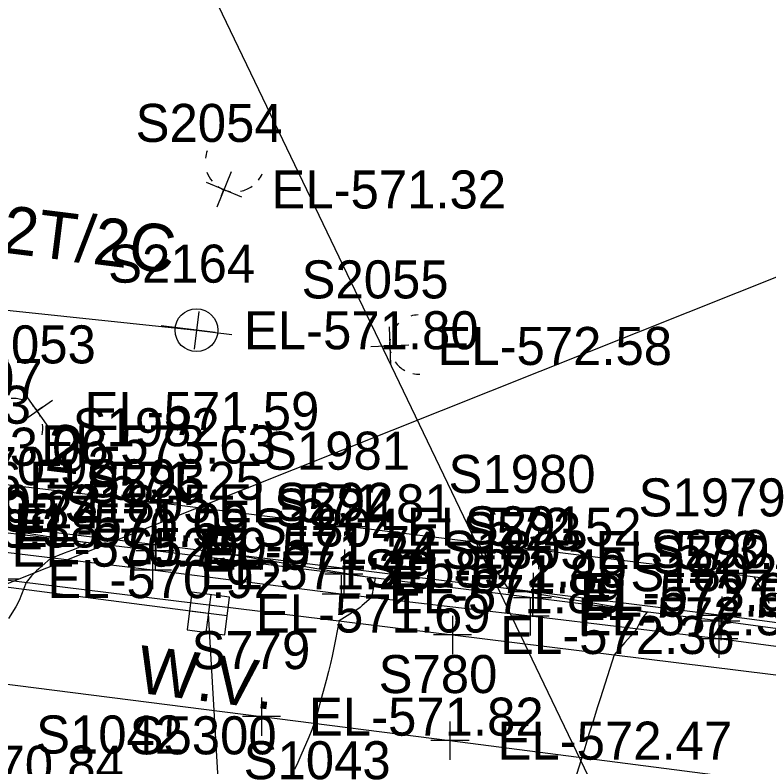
# Model space of a CAD drawing. Extents: x 1724534 to 1727318, y 657156 to 660047.
# Drawn here: x 1725826.2 to 1725905.5, y 658583.4 to 658662.4 of the extents above; entities that cross this region are included whole.
import ezdxf

# ---------------------------------------------------------------- set-up
doc = ezdxf.new("R2010")
doc.units = 0
for name, color, linetype in [('SURVEY - CENTERLINE - Preliminary Text', 7, 'Continuous'), ('SURVEY - CONTOURS - Intermediate with optional Text', 7, 'Continuous'), ('SURVEY - DRAINAGE - Storm Sewer', 7, 'Continuous'), ('SURVEY - DTM - Breaklines', 7, 'Continuous'), ('SURVEY - DTM - Breaklines - Points - Elevations', 7, 'Continuous'), ('SURVEY - DTM - Breaklines - Points - Locators', 7, 'Continuous'), ('SURVEY - DTM - Breaklines - Points - Numbers', 7, 'Continuous'), ('SURVEY - ROADSIDE BARRIERS - Points - Elevations', 7, 'Continuous'), ('SURVEY - ROADSIDE BARRIERS - Points - Numbers', 7, 'Continuous'), ('SURVEY - TRAFFIC CONTROL - Pavement Marking - Points - Elevations', 7, 'Continuous'), ('SURVEY - TRAFFIC CONTROL - Pavement Marking - Points - Locators', 7, 'Continuous'), ('SURVEY - TRAFFIC CONTROL - Pavement Marking - Points - Numbers', 7, 'Continuous'), ('SURVEY - TRAFFIC CONTROL - Pavement Marking with Text', 7, 'Continuous'), ('SURVEY - TRANSPORTATION - Features', 7, 'Continuous'), ('SURVEY - TRANSPORTATION - Features - Points - Elevations', 7, 'Continuous'), ('SURVEY - TRANSPORTATION - Features - Points - Locators', 7, 'Continuous'), ('SURVEY - TRANSPORTATION - Features - Points - Numbers', 7, 'Continuous'), ('SURVEY - TRANSPORTATION - Roads', 7, 'Continuous'), ('SURVEY - TRANSPORTATION - Roads - Points - Elevations', 7, 'Continuous'), ('SURVEY - TRANSPORTATION - Roads - Points - Locators', 7, 'Continuous'), ('SURVEY - TRANSPORTATION - Roads - Points - Numbers', 7, 'Continuous'), ('SURVEY - UTILITIES - Overhead Wire Crossings', 7, 'Continuous'), ('SURVEY - UTILITIES - Poles and Miscellaneous - Points - Elevations', 7, 'Continuous'), ('SURVEY - UTILITIES - Poles and Miscellaneous - Points - Locators', 7, 'Continuous'), ('SURVEY - UTILITIES - Poles and Miscellaneous - Points - Numbers', 7, 'Continuous'), ('SURVEY - UTILITIES - Poles and Miscellaneous with Text', 7, 'Continuous'), ('SURVEY - UTILITIES - Water - Points - Elevations', 7, 'Continuous'), ('SURVEY - UTILITIES - Water - Points - Locators', 7, 'Continuous'), ('SURVEY - UTILITIES - Water - Points - Numbers', 7, 'Continuous'), ('SURVEY - UTILITIES - Water with Text', 7, 'Continuous')]:
    doc.layers.add(name, color=color, linetype=linetype)

msp = doc.modelspace()

# ---------------------------------------------------------------- linework, layer by layer
at = {"layer": 'SURVEY - CENTERLINE - Preliminary Text'}
msp.add_line((1725772.853, 658581.708), (1725925.415, 658642.543), dxfattribs=at)
at = {"layer": 'SURVEY - CONTOURS - Intermediate with optional Text'}
for points in [[(1725846.883, 658610.445), (1725847.229, 658609.737), (1725847.817, 658608.493), (1725849.121, 658605.72), (1725851.058, 658605.397), (1725851.572, 658605.312), (1725852.077, 658605.228), (1725856.35, 658604.519), (1725858.166, 658604.22), (1725859.028, 658604.079), (1725859.647, 658603.976), (1725860.528, 658603.83), (1725860.808, 658603.784), (1725860.87, 658603.774), (1725861.796, 658603.619), (1725864.101, 658603.234), (1725863.926, 658602.302), (1725863.891, 658602.114), (1725863.857, 658601.949), (1725863.827, 658601.807), (1725863.8, 658601.687), (1725863.678, 658601.184), (1725862.72, 658600.344), (1725862.503, 658600.163), (1725862.262, 658599.98), (1725861.998, 658599.795), (1725861.709, 658599.609), (1725860.307, 658598.732), (1725859.707, 658595.722), (1725859.562, 658595.036), (1725859.385, 658594.269), (1725859.175, 658593.421), (1725858.933, 658592.491), (1725858.245, 658589.903), (1725857.98, 658588.963), (1725857.702, 658588.086), (1725857.412, 658587.272), (1725857.108, 658586.519), (1725856.281, 658584.597), (1725855.954, 658583.868), (1725855.595, 658583.124)], [(1725826.087, 658608.215), (1725826.634, 658608.127), (1725827.177, 658608.039), (1725828.622, 658607.807), (1725829.121, 658607.726), (1725829.534, 658607.66), (1725829.861, 658607.607), (1725830.103, 658607.568), (1725830.858, 658607.447), (1725831.134, 658607.403), (1725831.462, 658607.35), (1725831.841, 658607.289), (1725833.73, 658606.984), (1725833.032, 658606.535), (1725832.865, 658606.438), (1725832.663, 658606.339), (1725832.427, 658606.238), (1725832.156, 658606.135), (1725831.387, 658605.859), (1725831.127, 658605.764), (1725830.923, 658605.689), (1725830.776, 658605.632), (1725830.685, 658605.594), (1725830.518, 658605.518), (1725830.456, 658605.491), (1725830.393, 658605.466), (1725830.33, 658605.445), (1725830.267, 658605.427), (1725829.971, 658605.349), (1725828.715, 658604.232), (1725828.465, 658604.005), (1725828.252, 658603.801), (1725828.076, 658603.622), (1725827.938, 658603.466), (1725827.378, 658602.797), (1725826.642, 658600.898), (1725826.282, 658600.218), (1725825.518, 658598.99)], [(1725874.865, 658606.982), (1725875.917, 658605.357), (1725876.397, 658604.627), (1725878.066, 658602.116), (1725880.271, 658601.747), (1725880.867, 658601.648), (1725881.631, 658601.52), (1725886.772, 658600.663), (1725888.832, 658600.319), (1725892.705, 658599.672), (1725892.341, 658599.253), (1725892.261, 658599.152), (1725892.178, 658599.029), (1725892.091, 658598.884), (1725892.001, 658598.717), (1725891.571, 658597.887), (1725890.939, 658597.147), (1725890.358, 658596.477), (1725889.218, 658595.164), (1725887.782, 658590.658), (1725887.444, 658589.589), (1725887.043, 658588.312), (1725886.58, 658586.829), (1725886.056, 658585.138), (1725884.574, 658580.353)], [(1725903.921, 658603.36), (1725904.459, 658602.513), (1725904.579, 658602.319), (1725904.708, 658602.102), (1725904.846, 658601.861), (1725904.993, 658601.596), (1725905.542, 658600.595)]]:
    msp.add_lwpolyline(points, dxfattribs=at)
at = {"layer": 'SURVEY - DRAINAGE - Storm Sewer'}
msp.add_line((1725899.095, 658556.269), (1725845.926, 658666.932), dxfattribs=at)
at = {"layer": 'SURVEY - DTM - Breaklines'}
msp.add_lwpolyline([(1725923.442, 658596.261), (1725920.349, 658596.664), (1725900.537, 658599.315), (1725880.703, 658601.788), (1725860.867, 658604.256), (1725841.017, 658606.73), (1725821.164, 658609.108), (1725805.637, 658611.084), (1725785.8, 658613.524), (1725762.697, 658616.458), (1725748.853, 658618.143), (1725745.613, 658618.535), (1725725.762, 658620.955), (1725705.909, 658623.419), (1725686.061, 658625.875)], dxfattribs=at)
at = {"layer": 'SURVEY - DTM - Breaklines - Points - Locators'}
for p, q in [((1725841.017, 658608.73), (1725841.017, 658604.73)), ((1725843.017, 658606.73), (1725839.017, 658606.73)), ((1725860.867, 658606.256), (1725860.867, 658602.256)), ((1725862.867, 658604.256), (1725858.867, 658604.256)), ((1725880.703, 658603.788), (1725880.703, 658599.788)), ((1725882.703, 658601.788), (1725878.703, 658601.788)), ((1725900.537, 658601.315), (1725900.537, 658597.315)), ((1725902.537, 658599.315), (1725898.537, 658599.315))]:
    msp.add_line(p, q, dxfattribs=at)
at = {"layer": 'SURVEY - TRAFFIC CONTROL - Pavement Marking - Points - Locators'}
for p, q in [((1725852.127, 658590.674), (1725852.127, 658586.674)), ((1725854.127, 658588.674), (1725850.127, 658588.674)), ((1725871.961, 658588.151), (1725871.961, 658584.151)), ((1725873.961, 658586.151), (1725869.961, 658586.151))]:
    msp.add_line(p, q, dxfattribs=at)
at = {"layer": 'SURVEY - TRAFFIC CONTROL - Pavement Marking with Text'}
msp.add_lwpolyline([(1725469.93, 658636.195), (1725476.311, 658635.371), (1725478.295, 658635.122), (1725516.011, 658630.481), (1725599.369, 658620.164), (1725678.757, 658610.338), (1725738.298, 658602.97), (1725780.716, 658597.719), (1725790.639, 658596.491), (1725852.127, 658588.674), (1725871.961, 658586.151), (1725916.153, 658580.463)], dxfattribs=at)
at = {"layer": 'SURVEY - TRANSPORTATION - Features'}
for points in [[(1725923.364, 658595.652), (1725920.271, 658596.054), (1725900.459, 658598.705), (1725880.625, 658601.178), (1725860.79, 658603.646), (1725840.941, 658606.12), (1725821.088, 658608.498), (1725805.562, 658610.474), (1725785.723, 658612.914), (1725762.62, 658615.849), (1725748.776, 658617.533), (1725745.535, 658617.925), (1725725.684, 658620.345), (1725705.833, 658622.809), (1725685.985, 658625.265)], [(1725924.124, 658601.632), (1725920.917, 658601.133), (1725901.098, 658603.73), (1725881.263, 658606.193), (1725861.425, 658608.639), (1725841.56, 658611.106), (1725821.706, 658613.473), (1725806.126, 658615.02), (1725786.298, 658617.46), (1725763.169, 658620.191), (1725751.211, 658621.652), (1725751.19, 658622.534), (1725749.441, 658623.208)], [(1725923.129, 658593.802), (1725920.036, 658594.204), (1725900.224, 658596.854), (1725880.377, 658599.224), (1725860.524, 658601.554), (1725840.686, 658604.065), (1725820.833, 658606.443), (1725805.311, 658608.457), (1725785.478, 658610.975), (1725762.374, 658613.908), (1725762.62, 658615.849)]]:
    msp.add_lwpolyline(points, dxfattribs=at)
at = {"layer": 'SURVEY - TRANSPORTATION - Features - Points - Locators'}
for p, q in [((1725841.56, 658613.106), (1725841.56, 658609.106)), ((1725843.56, 658611.106), (1725839.56, 658611.106)), ((1725861.425, 658610.639), (1725861.425, 658606.639)), ((1725840.941, 658608.12), (1725840.941, 658604.12)), ((1725863.425, 658608.639), (1725859.425, 658608.639)), ((1725881.263, 658608.193), (1725881.263, 658604.193)), ((1725842.941, 658606.12), (1725838.941, 658606.12)), ((1725840.686, 658606.065), (1725840.686, 658602.065)), ((1725883.263, 658606.193), (1725879.263, 658606.193)), ((1725901.098, 658605.73), (1725901.098, 658601.73)), ((1725860.79, 658605.646), (1725860.79, 658601.646)), ((1725842.686, 658604.065), (1725838.686, 658604.065)), ((1725862.79, 658603.646), (1725858.79, 658603.646)), ((1725860.524, 658603.554), (1725860.524, 658599.554)), ((1725903.098, 658603.73), (1725899.098, 658603.73)), ((1725880.625, 658603.178), (1725880.625, 658599.178)), ((1725862.524, 658601.554), (1725858.524, 658601.554)), ((1725882.625, 658601.178), (1725878.625, 658601.178)), ((1725880.377, 658601.224), (1725880.377, 658597.224)), ((1725900.459, 658600.705), (1725900.459, 658596.705)), ((1725882.377, 658599.224), (1725878.377, 658599.224)), ((1725902.459, 658598.705), (1725898.459, 658598.705)), ((1725900.224, 658598.854), (1725900.224, 658594.854)), ((1725902.224, 658596.854), (1725898.224, 658596.854))]:
    msp.add_line(p, q, dxfattribs=at)
at = {"layer": 'SURVEY - TRANSPORTATION - Roads'}
msp.add_lwpolyline([(1725603.861, 658630.44), (1725726.921, 658615.268), (1725763.101, 658610.806), (1725790.88, 658607.344), (1725824.612, 658603.138), (1725872.227, 658597.261), (1725926.076, 658590.615)], dxfattribs=at)
at = {"layer": 'SURVEY - TRANSPORTATION - Roads - Points - Locators'}
for p, q in [((1725826.612, 658603.138), (1725822.612, 658603.138)), ((1725872.227, 658599.261), (1725872.227, 658595.261)), ((1725874.227, 658597.261), (1725870.227, 658597.261))]:
    msp.add_line(p, q, dxfattribs=at)
at = {"layer": 'SURVEY - UTILITIES - Overhead Wire Crossings'}
msp.add_line((1725320.87, 658684.66), (1725845.289, 658629.305), dxfattribs=at)
at = {"layer": 'SURVEY - UTILITIES - Poles and Miscellaneous - Points - Locators'}
for p, q in [((1725848.936, 658645.956), (1725847.422, 658642.254)), ((1725846.328, 658644.862), (1725850.03, 658643.348)), ((1725845.532, 658631.29), (1725845.046, 658627.32)), ((1725847.274, 658629.062), (1725843.304, 658629.548)), ((1725865.557, 658629.649), (1725865.711, 658625.651)), ((1725867.633, 658627.727), (1725863.635, 658627.573)), ((1725829.685, 658619.181), (1725827.381, 658622.451)), ((1725826.898, 658619.664), (1725830.168, 658621.968))]:
    msp.add_line(p, q, dxfattribs=at)
at = {"layer": 'SURVEY - UTILITIES - Poles and Miscellaneous with Text'}
for p, q in [((1725847.914, 658643.457), (1725848.179, 658644.105)), ((1725845.289, 658629.305), (1725841.567, 658629.76)), ((1725845.289, 658629.305), (1725849.011, 658628.85)), ((1725864.935, 658627.623), (1725865.634, 658627.65)), ((1725829.105, 658621.219), (1725828.533, 658620.816))]:
    msp.add_line(p, q, dxfattribs=at)
msp.add_circle((1725845.289, 658629.305), 2.25, dxfattribs=at)
for centre, start, end in [((1725849.329, 658646.984), 157.76371, 172.38458), ((1725849.329, 658646.984), 199.64158, 219.98409), ((1725849.329, 658646.984), 322.95024, 336.83966), ((1725849.329, 658646.984), 235.28464, 261.79995), ((1725849.329, 658646.984), 281.32645, 306.09649), ((1725868.731, 658627.794), 92.2058, 106.82667), ((1725868.731, 658627.794), 134.08367, 154.42618), ((1725868.731, 658627.794), 169.72673, 196.24204), ((1725868.731, 658627.794), 215.76854, 240.53858), ((1725868.731, 658627.794), 257.39233, 271.28175), ((1725826.014, 658619.01), 68.73872, 93.50876), ((1725826.014, 658619.01), 22.6969, 49.21222), ((1725826.014, 658619.01), 347.05385, 7.39636), ((1725826.014, 658619.01), 305.17598, 319.79685)]:
    msp.add_arc(centre, 3.125, start, end, dxfattribs=at)
at = {"layer": 'SURVEY - UTILITIES - Water - Points - Locators'}
for p, q in [((1725846.804, 658601.504), (1725846.292, 658597.536)), ((1725848.532, 658599.264), (1725844.564, 658599.776))]:
    msp.add_line(p, q, dxfattribs=at)
at = {"layer": 'SURVEY - UTILITIES - Water with Text'}
msp.add_line((1725846.548, 658599.52), (1725846.548, 658599.52), dxfattribs=at)
for points in [[(1725847.724, 658579.712), (1725846.548, 658599.52), (1725380.522, 658660.104)], [(1725844.82, 658601.759), (1725844.309, 658597.792), (1725848.276, 658597.281), (1725848.787, 658601.248), (1725844.82, 658601.759)]]:
    msp.add_lwpolyline(points, dxfattribs=at)

# ---------------------------------------------------------------- texts
at = {"layer": 'SURVEY - DTM - Breaklines - Points - Elevations'}
for s, p in [('EL-570.72', (1725810.637, 658609.084)), ('EL-571.09', (1725826.164, 658607.108)), ('EL-571.72', (1725846.017, 658604.73)), ('EL-572.40', (1725865.867, 658602.256)), ('EL-573.09', (1725885.703, 658599.788))]:
    msp.add_text(s, height=4, dxfattribs=at).set_placement(p)
at = {"layer": 'SURVEY - DTM - Breaklines - Points - Numbers'}
for s, p in [('S293', (1725833.681, 658611.73)), ('S292', (1725853.531, 658609.256)), ('S291', (1725873.525, 658606.788)), ('S290', (1725893.028, 658604.315))]:
    msp.add_text(s, height=4, dxfattribs=at).set_placement(p)
at = {"layer": 'SURVEY - ROADSIDE BARRIERS - Points - Elevations'}
for s, p in [('EL-573.63', (1725828.955, 658615.289)), ('EL-573.06', (1725811.38, 658615.061))]:
    msp.add_text(s, height=4, dxfattribs=at).set_placement(p)
at = {"layer": 'SURVEY - ROADSIDE BARRIERS - Points - Numbers'}
msp.add_text('S707', height=4, dxfattribs=at).set_placement((1725816.619, 658622.289))
at = {"layer": 'SURVEY - TRAFFIC CONTROL - Pavement Marking - Points - Elevations'}
for s, p in [('EL-571.82', (1725857.127, 658586.674)), ('EL-572.47', (1725876.961, 658584.151)), ('EL-570.84', (1725812.969, 658581.629))]:
    msp.add_text(s, height=4, dxfattribs=at).set_placement(p)
at = {"layer": 'SURVEY - TRAFFIC CONTROL - Pavement Marking - Points - Numbers'}
for s, p in [('S779', (1725844.775, 658593.674)), ('S780', (1725864.452, 658591.151)), ('S1042', (1725828.428, 658584.798)), ('S1043', (1725850.253, 658582.092))]:
    msp.add_text(s, height=4, dxfattribs=at).set_placement(p)
at = {"layer": 'SURVEY - TRANSPORTATION - Features - Points - Elevations'}
for s, p in [('EL-570.92', (1725812.126, 658613.02)), ('EL-571.25', (1725827.706, 658611.473)), ('EL-571.81', (1725847.56, 658609.106)), ('EL-570.24', (1725810.562, 658608.474)), ('EL-570.38', (1725810.311, 658606.457)), ('EL-570.58', (1725826.088, 658606.498)), ('EL-572.52', (1725867.425, 658606.639)), ('EL-570.75', (1725825.833, 658604.443)), ('EL-571.24', (1725845.941, 658604.12)), ('EL-573.23', (1725887.263, 658604.193)), ('EL-571.29', (1725845.686, 658602.065)), ('EL-571.88', (1725865.79, 658601.646)), ('EL-571.89', (1725865.524, 658599.554)), ('EL-572.58', (1725885.625, 658599.178)), ('EL-572.58', (1725885.377, 658597.224))]:
    msp.add_text(s, height=4, dxfattribs=at).set_placement(p)
at = {"layer": 'SURVEY - TRANSPORTATION - Features - Points - Numbers'}
for s, p in [('S1983', (1725812.418, 658619.473)), ('S1982', (1725832.272, 658617.106)), ('S1981', (1725852.295, 658614.639)), ('S1980', (1725871.802, 658612.193)), ('S1806', (1725811.435, 658611.443)), ('S525', (1725833.605, 658611.12)), ('S1979', (1725891.795, 658609.73)), ('S1805', (1725831.398, 658609.065)), ('S524', (1725853.454, 658608.646)), ('S1804', (1725851.236, 658606.554)), ('S523', (1725873.289, 658606.178)), ('S1803', (1725871.089, 658604.224)), ('S522', (1725893.123, 658603.705)), ('S1802', (1725890.936, 658601.854))]:
    msp.add_text(s, height=4, dxfattribs=at).set_placement(p)
at = {"layer": 'SURVEY - TRANSPORTATION - Roads - Points - Elevations'}
for s, p in [('EL-570.92', (1725829.612, 658601.138)), ('EL-572.36', (1725877.227, 658595.261))]:
    msp.add_text(s, height=4, dxfattribs=at).set_placement(p)
at = {"layer": 'SURVEY - TRANSPORTATION - Roads - Points - Numbers'}
for s, p in [('S1588', (1725815.277, 658608.138)), ('S1589', (1725862.924, 658602.261))]:
    msp.add_text(s, height=4, dxfattribs=at).set_placement(p)
at = {"layer": 'SURVEY - UTILITIES - Poles and Miscellaneous - Points - Elevations'}
for s, p in [('EL-571.32', (1725853.179, 658642.105)), ('EL-571.80', (1725850.289, 658627.305)), ('EL-572.58', (1725870.634, 658625.65)), ('EL-571.59', (1725833.533, 658618.816))]:
    msp.add_text(s, height=4, dxfattribs=at).set_placement(p)
at = {"layer": 'SURVEY - UTILITIES - Poles and Miscellaneous - Points - Numbers'}
for s, p in [('S2054', (1725838.891, 658649.105)), ('S2164', (1725836.001, 658634.305)), ('S2055', (1725856.346, 658632.65)), ('S2053', (1725819.245, 658625.816))]:
    msp.add_text(s, height=4, dxfattribs=at).set_placement(p)
at = {"layer": 'SURVEY - UTILITIES - Poles and Miscellaneous with Text'}
for s, rotation, p in [('6P/2T/2C', 352.86411, (1725814.722, 658638.749)), ('2', 353.02638, (1725829.247, 658614.582))]:
    msp.add_text(s, height=5, rotation=rotation, dxfattribs=at).set_placement(p)
at = {"layer": 'SURVEY - UTILITIES - Water - Points - Elevations'}
msp.add_text('EL-571.69', height=4, dxfattribs=at).set_placement((1725851.548, 658597.52))
at = {"layer": 'SURVEY - UTILITIES - Water - Points - Numbers'}
for s, p in [('S5299', (1725837.245, 658604.52)), ('S5300', (1725838.263, 658584.712))]:
    msp.add_text(s, height=4, dxfattribs=at).set_placement(p)
at = {"layer": 'SURVEY - UTILITIES - Water with Text'}
msp.add_text('W.V.', height=5.0001, rotation=352.65747, dxfattribs=at).set_placement((1725838.876, 658591.233))

doc.saveas('drawing.dxf')
